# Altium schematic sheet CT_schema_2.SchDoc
size 271 x 229 mm
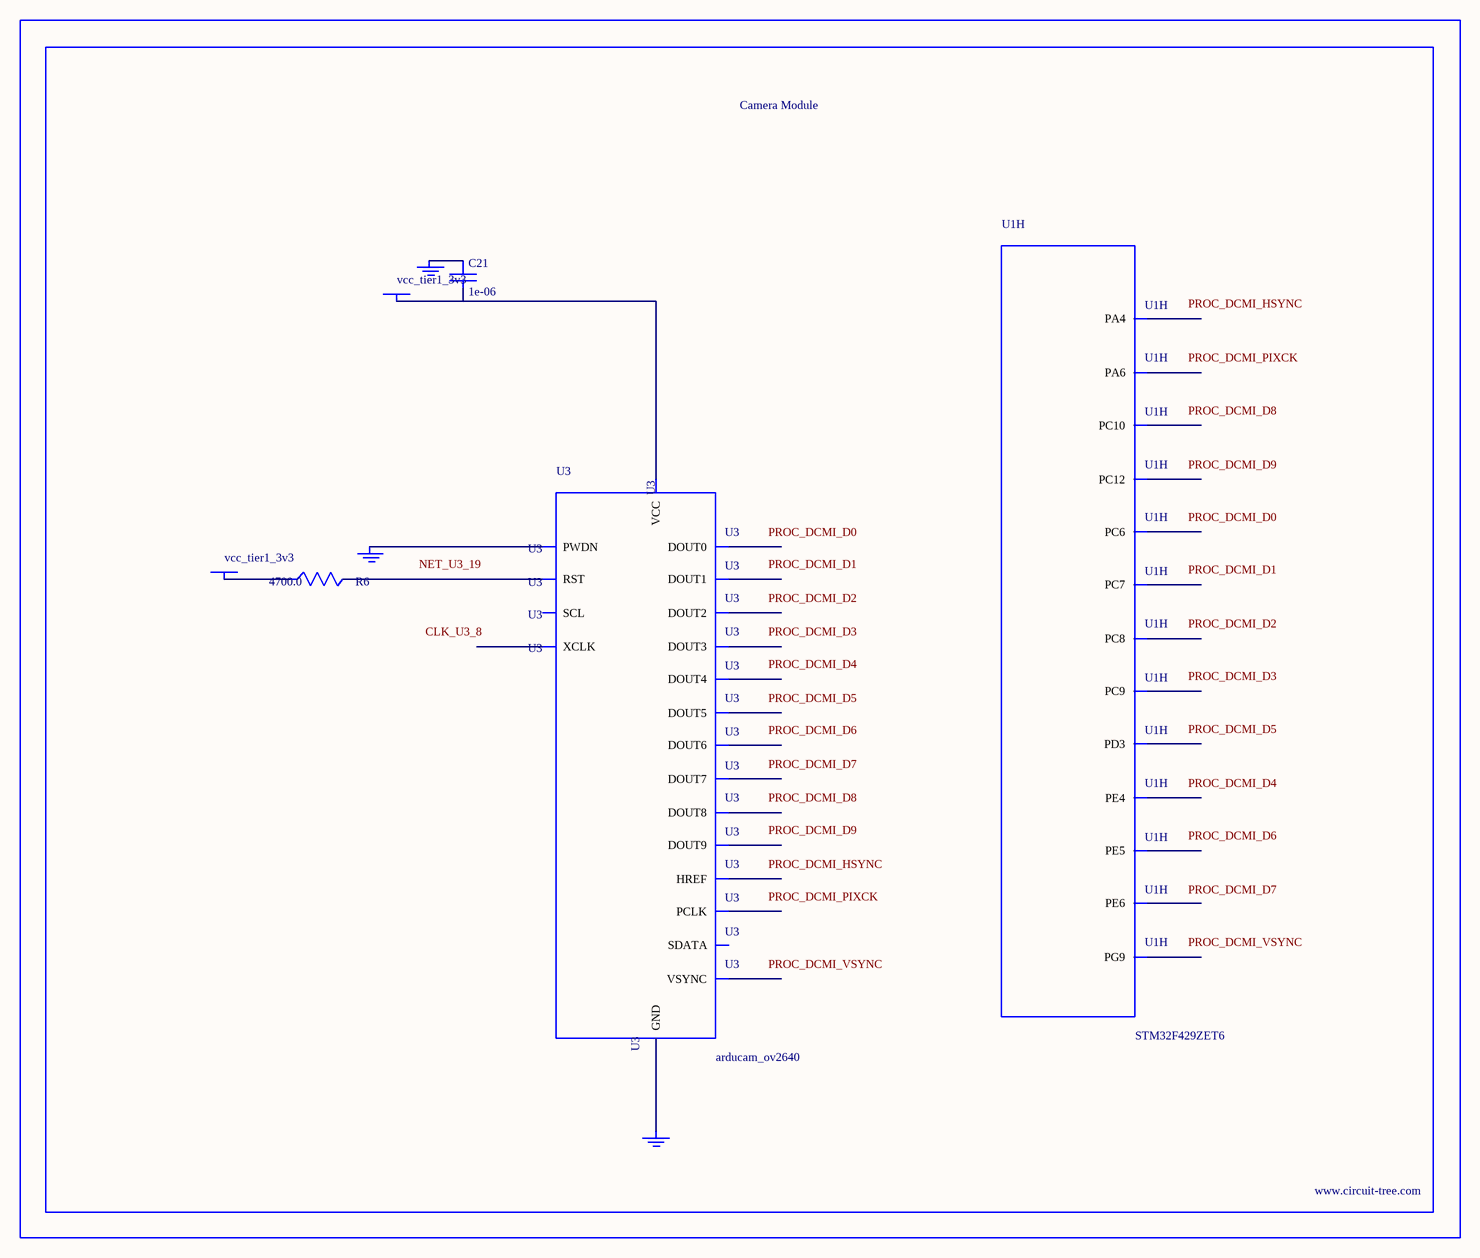
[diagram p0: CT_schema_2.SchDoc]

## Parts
BORDER1  (no value)
C21  1e-06  [C0603]
GND_INSTANCE_1_0  (no value)
GND_INSTANCE_1_1  (no value)
GND_INSTANCE_1_2  (no value)
POWER_INSTANCE_1_0  vcc_tier1_3v3
POWER_INSTANCE_1_1  vcc_tier1_3v3
R6  4700.0  [R0603]
U1  STM32F429ZET6  [LQFP144]  (part H of 11)
U3  arducam_ov2640  [ARDUCAM]

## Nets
NetC21_1: C21.1 GND_INSTANCE_1_0.0(GND)
NetC21_2: C21.2 POWER_INSTANCE_1_0.0(PWR) U3.1(VCC)
NetGND_INSTANCE_1_1_0: GND_INSTANCE_1_1.0(GND) U3.20(PWDN)
NetGND_INSTANCE_1_2_0: GND_INSTANCE_1_2.0(GND) U3.2(GND)
NetPOWER_INSTANCE_1_1_0: POWER_INSTANCE_1_1.0(PWR) R6.1
NetR6_2: R6.2 U3.19(RST)

Not connected (* = marked no-connect by the designer): U1 3(PE4) 4(PE5) 5(PE6) 40(PA4) 42(PA6) 96(PC6) 97(PC7) 98(PC8) 99(PC9) 111(PC10) 113(PC12) 117(PD3) 124(PG9); U3 3(SCL) 4(SDATA) 5(VSYNC) 6(HREF) 7(PCLK) 8(XCLK) 9(DOUT9) 10(DOUT8) 11(DOUT7) 12(DOUT6) 13(DOUT5) 14(DOUT4) 15(DOUT3) 16(DOUT2) 17(DOUT1) 18(DOUT0)

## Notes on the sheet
- Labels drawn without touching a wire or pin: CLK_U3_8, NET_U3_19, PROC_DCMI_D0, PROC_DCMI_D1, PROC_DCMI_D2, PROC_DCMI_D3, PROC_DCMI_D4, PROC_DCMI_D5, PROC_DCMI_D6, PROC_DCMI_D7, PROC_DCMI_D8, PROC_DCMI_D9, PROC_DCMI_HSYNC, PROC_DCMI_PIXCK, PROC_DCMI_VSYNC

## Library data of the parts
BORDER1 = BORDER_PAGE1
C21 = C0603C105K3RACTU
GND_INSTANCE_1_0-GND_INSTANCE_1_2 = GND
POWER_INSTANCE_1_0 POWER_INSTANCE_1_1 = PWR
R6 = RC0603JR-074K7L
